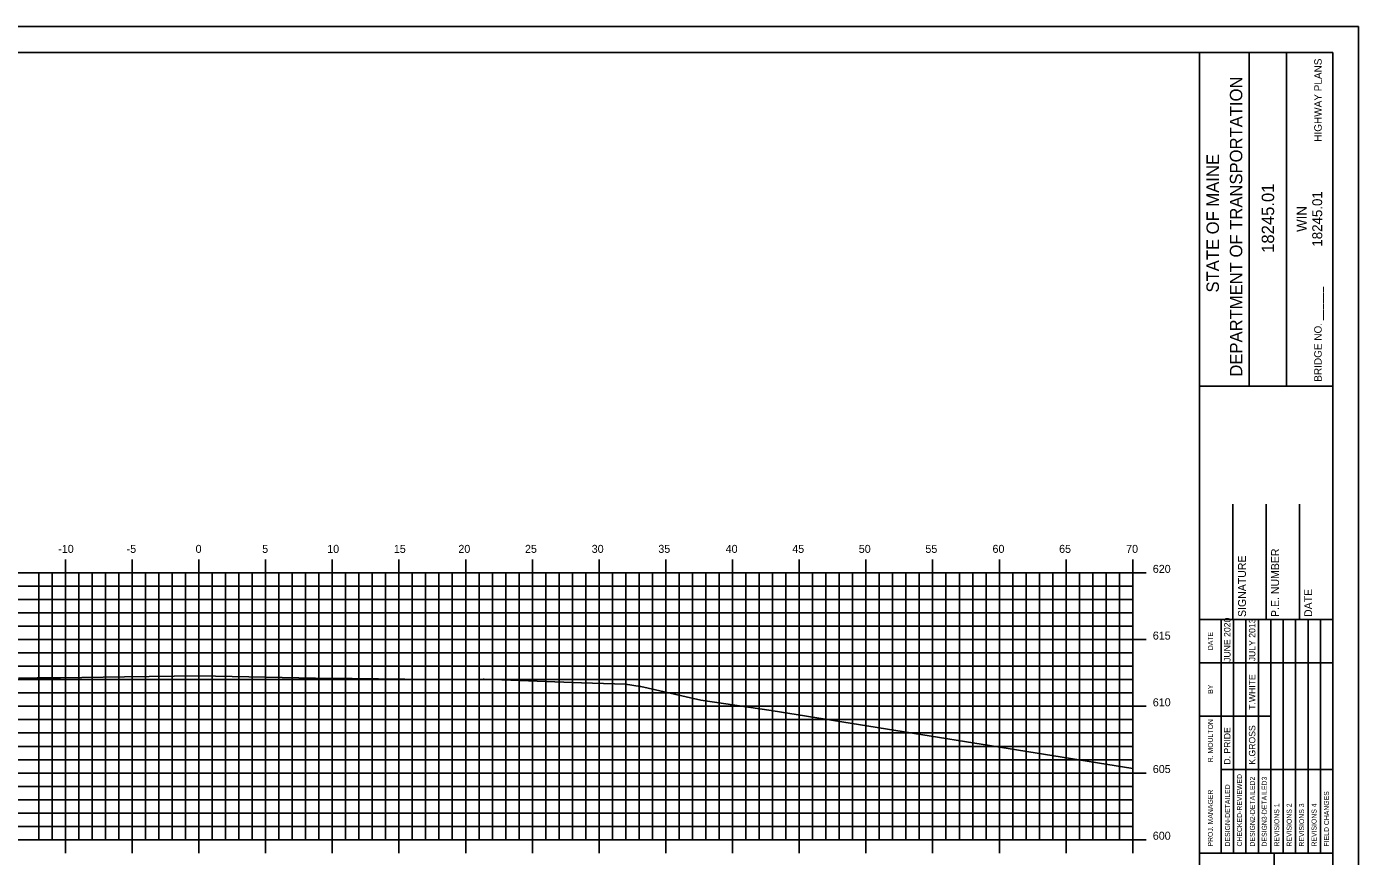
# Model space of a CAD drawing. Extents: x 1048806 to 1048976, y 780904 to 781014.
# Drawn here: x 1048876.1 to 1048975.9, y 780951.9 to 781014.1 of the extents above; entities that cross this region are included whole.
import ezdxf

# ---------------------------------------------------------------- set-up
doc = ezdxf.new("R2010")
doc.units = 0
for name, color, linetype in [('BORDER', 7, 'Continuous'), ('Default', 7, 'Continuous'), ('H_V ANNOTATION', 7, 'Continuous'), ('MAJOR', 7, 'Continuous'), ('MINOR', 7, 'Continuous'), ('S_Roadway_Centerline', 7, 'Continuous')]:
    doc.layers.add(name, color=color, linetype=linetype)

msp = doc.modelspace()

# ---------------------------------------------------------------- linework, layer by layer
at = {"layer": 'Default'}
for p, q in [((1048973.983, 781012.114), (1048813.983, 781012.114)), ((1048963.983, 780907.114), (1048963.983, 781012.117)), ((1048967.711, 780987.111), (1048967.711, 781012.111)), ((1048970.506, 780987.111), (1048970.506, 781012.111)), ((1048973.983, 780907.114), (1048973.983, 781012.114)), ((1048963.984, 780987.108), (1048973.983, 780987.108)), ((1048966.483, 780969.617), (1048966.483, 780978.265)), ((1048968.983, 780969.617), (1048968.983, 780978.265)), ((1048971.483, 780969.617), (1048971.483, 780978.265)), ((1048963.983, 780969.617), (1048973.983, 780969.617)), ((1048963.983, 780952.117), (1048973.983, 780952.117)), ((1048969.574, 780917.117), (1048969.574, 780952.117))]:
    msp.add_line(p, q, dxfattribs=at)
msp.add_lwpolyline([(1048805.889, 780904.055), (1048975.889, 780904.055), (1048975.889, 781014.055), (1048805.889, 781014.055)], close=True, dxfattribs=at)
for points in [[(1048965.598, 780966.367), (1048965.598, 780969.617)], [(1048966.53, 780952.12), (1048966.53, 780969.617)], [(1048967.462, 780969.617), (1048967.462, 780952.12)], [(1048968.394, 780952.12), (1048968.394, 780969.617)], [(1048969.325, 780952.12), (1048969.325, 780969.617)], [(1048970.257, 780952.12), (1048970.257, 780969.617)], [(1048971.189, 780952.12), (1048971.189, 780969.617)], [(1048972.12, 780952.12), (1048972.12, 780969.617)], [(1048973.052, 780952.12), (1048973.052, 780969.617)], [(1048965.599, 780952.12), (1048965.599, 780968.911)], [(1048963.983, 780966.367), (1048973.983, 780966.367)], [(1048963.983, 780962.367), (1048965.599, 780962.367)], [(1048965.598, 780962.367), (1048969.324, 780962.367)], [(1048965.598, 780958.367), (1048973.983, 780958.367)]]:
    msp.add_lwpolyline(points, dxfattribs=at)
at = {"layer": 'MAJOR'}
for p, q in [((1048878.983, 780974.116), (1048878.983, 780973.114)), ((1048883.983, 780974.116), (1048883.983, 780973.114)), ((1048888.983, 780974.116), (1048888.983, 780973.114)), ((1048893.983, 780974.116), (1048893.983, 780973.114)), ((1048898.983, 780974.116), (1048898.983, 780973.114)), ((1048903.983, 780974.116), (1048903.983, 780973.114)), ((1048908.983, 780974.116), (1048908.983, 780973.114)), ((1048913.983, 780974.116), (1048913.983, 780973.114)), ((1048918.983, 780974.116), (1048918.983, 780973.114)), ((1048923.983, 780974.116), (1048923.983, 780973.114)), ((1048928.983, 780974.116), (1048928.983, 780973.114)), ((1048933.983, 780974.116), (1048933.983, 780973.114)), ((1048938.983, 780974.116), (1048938.983, 780973.114)), ((1048943.983, 780974.116), (1048943.983, 780973.114)), ((1048948.983, 780974.116), (1048948.983, 780973.114)), ((1048953.983, 780974.116), (1048953.983, 780973.114)), ((1048958.983, 780974.116), (1048958.983, 780973.114)), ((1048818.983, 780973.114), (1048958.983, 780973.114)), ((1048818.983, 780973.114), (1048958.983, 780973.114)), ((1048878.983, 780953.114), (1048878.983, 780973.114)), ((1048883.983, 780953.114), (1048883.983, 780973.114)), ((1048888.983, 780953.114), (1048888.983, 780973.114)), ((1048893.983, 780953.114), (1048893.983, 780973.114)), ((1048898.983, 780953.114), (1048898.983, 780973.114)), ((1048903.983, 780953.114), (1048903.983, 780973.114)), ((1048908.983, 780953.114), (1048908.983, 780973.114)), ((1048913.983, 780953.114), (1048913.983, 780973.114)), ((1048918.983, 780953.114), (1048918.983, 780973.114)), ((1048923.983, 780953.114), (1048923.983, 780973.114)), ((1048928.983, 780953.114), (1048928.983, 780973.114)), ((1048933.983, 780953.114), (1048933.983, 780973.114)), ((1048938.983, 780953.114), (1048938.983, 780973.114)), ((1048943.983, 780953.114), (1048943.983, 780973.114)), ((1048948.983, 780953.114), (1048948.983, 780973.114)), ((1048953.983, 780953.114), (1048953.983, 780973.114)), ((1048959.985, 780973.114), (1048957.981, 780973.114)), ((1048958.983, 780953.114), (1048958.983, 780973.114)), ((1048958.983, 780953.114), (1048958.983, 780973.114)), ((1048818.983, 780968.114), (1048958.983, 780968.114)), ((1048959.985, 780968.114), (1048957.981, 780968.114)), ((1048818.983, 780963.114), (1048958.983, 780963.114)), ((1048959.985, 780963.114), (1048957.981, 780963.114)), ((1048818.983, 780958.114), (1048958.983, 780958.114)), ((1048959.985, 780958.114), (1048957.981, 780958.114)), ((1048818.983, 780953.114), (1048958.983, 780953.114)), ((1048818.983, 780953.114), (1048958.983, 780953.114)), ((1048878.983, 780952.112), (1048878.983, 780953.114)), ((1048883.983, 780952.112), (1048883.983, 780953.114)), ((1048888.983, 780952.112), (1048888.983, 780953.114)), ((1048893.983, 780952.112), (1048893.983, 780953.114)), ((1048898.983, 780952.112), (1048898.983, 780953.114)), ((1048903.983, 780952.112), (1048903.983, 780953.114)), ((1048908.983, 780952.112), (1048908.983, 780953.114)), ((1048913.983, 780952.112), (1048913.983, 780953.114)), ((1048918.983, 780952.112), (1048918.983, 780953.114)), ((1048923.983, 780952.112), (1048923.983, 780953.114)), ((1048928.983, 780952.112), (1048928.983, 780953.114)), ((1048933.983, 780952.112), (1048933.983, 780953.114)), ((1048938.983, 780952.112), (1048938.983, 780953.114)), ((1048943.983, 780952.112), (1048943.983, 780953.114)), ((1048948.983, 780952.112), (1048948.983, 780953.114)), ((1048953.983, 780952.112), (1048953.983, 780953.114)), ((1048959.985, 780953.114), (1048957.981, 780953.114)), ((1048958.983, 780952.112), (1048958.983, 780953.114))]:
    msp.add_line(p, q, dxfattribs=at)
at = {"layer": 'MINOR'}
for p, q in [((1048876.983, 780953.114), (1048876.983, 780973.114)), ((1048877.983, 780953.114), (1048877.983, 780973.114)), ((1048879.983, 780953.114), (1048879.983, 780973.114)), ((1048880.983, 780953.114), (1048880.983, 780973.114)), ((1048881.983, 780953.114), (1048881.983, 780973.114)), ((1048882.983, 780953.114), (1048882.983, 780973.114)), ((1048884.983, 780953.114), (1048884.983, 780973.114)), ((1048885.983, 780953.114), (1048885.983, 780973.114)), ((1048886.983, 780953.114), (1048886.983, 780973.114)), ((1048887.983, 780953.114), (1048887.983, 780973.114)), ((1048889.983, 780953.114), (1048889.983, 780973.114)), ((1048890.983, 780953.114), (1048890.983, 780973.114)), ((1048891.983, 780953.114), (1048891.983, 780973.114)), ((1048892.983, 780953.114), (1048892.983, 780973.114)), ((1048894.983, 780953.114), (1048894.983, 780973.114)), ((1048895.983, 780953.114), (1048895.983, 780973.114)), ((1048896.983, 780953.114), (1048896.983, 780973.114)), ((1048897.983, 780953.114), (1048897.983, 780973.114)), ((1048899.983, 780953.114), (1048899.983, 780973.114)), ((1048900.983, 780953.114), (1048900.983, 780973.114)), ((1048901.983, 780953.114), (1048901.983, 780973.114)), ((1048902.983, 780953.114), (1048902.983, 780973.114)), ((1048904.983, 780953.114), (1048904.983, 780973.114)), ((1048905.983, 780953.114), (1048905.983, 780973.114)), ((1048906.983, 780953.114), (1048906.983, 780973.114)), ((1048907.983, 780953.114), (1048907.983, 780973.114)), ((1048909.983, 780953.114), (1048909.983, 780973.114)), ((1048910.983, 780953.114), (1048910.983, 780973.114)), ((1048911.983, 780953.114), (1048911.983, 780973.114)), ((1048912.983, 780953.114), (1048912.983, 780973.114)), ((1048914.983, 780953.114), (1048914.983, 780973.114)), ((1048915.983, 780953.114), (1048915.983, 780973.114)), ((1048916.983, 780953.114), (1048916.983, 780973.114)), ((1048917.983, 780953.114), (1048917.983, 780973.114)), ((1048919.983, 780953.114), (1048919.983, 780973.114)), ((1048920.983, 780953.114), (1048920.983, 780973.114)), ((1048921.983, 780953.114), (1048921.983, 780973.114)), ((1048922.983, 780953.114), (1048922.983, 780973.114)), ((1048924.983, 780953.114), (1048924.983, 780973.114)), ((1048925.983, 780953.114), (1048925.983, 780973.114)), ((1048926.983, 780953.114), (1048926.983, 780973.114)), ((1048927.983, 780953.114), (1048927.983, 780973.114)), ((1048929.983, 780953.114), (1048929.983, 780973.114)), ((1048930.983, 780953.114), (1048930.983, 780973.114)), ((1048931.983, 780953.114), (1048931.983, 780973.114)), ((1048932.983, 780953.114), (1048932.983, 780973.114)), ((1048934.983, 780953.114), (1048934.983, 780973.114)), ((1048935.983, 780953.114), (1048935.983, 780973.114)), ((1048936.983, 780953.114), (1048936.983, 780973.114)), ((1048937.983, 780953.114), (1048937.983, 780973.114)), ((1048939.983, 780953.114), (1048939.983, 780973.114)), ((1048940.983, 780953.114), (1048940.983, 780973.114)), ((1048941.983, 780953.114), (1048941.983, 780973.114)), ((1048942.983, 780953.114), (1048942.983, 780973.114)), ((1048944.983, 780953.114), (1048944.983, 780973.114)), ((1048945.983, 780953.114), (1048945.983, 780973.114)), ((1048946.983, 780953.114), (1048946.983, 780973.114)), ((1048947.983, 780953.114), (1048947.983, 780973.114)), ((1048949.983, 780953.114), (1048949.983, 780973.114)), ((1048950.983, 780953.114), (1048950.983, 780973.114)), ((1048951.983, 780953.114), (1048951.983, 780973.114)), ((1048952.983, 780953.114), (1048952.983, 780973.114)), ((1048954.983, 780953.114), (1048954.983, 780973.114)), ((1048955.983, 780953.114), (1048955.983, 780973.114)), ((1048956.983, 780953.114), (1048956.983, 780973.114)), ((1048957.983, 780953.114), (1048957.983, 780973.114)), ((1048818.983, 780972.114), (1048958.983, 780972.114)), ((1048958.983, 780972.114), (1048957.981, 780972.114)), ((1048818.983, 780971.114), (1048958.983, 780971.114)), ((1048958.983, 780971.114), (1048957.981, 780971.114)), ((1048818.983, 780970.114), (1048958.983, 780970.114)), ((1048958.983, 780970.114), (1048957.981, 780970.114)), ((1048818.983, 780969.114), (1048958.983, 780969.114)), ((1048958.983, 780969.114), (1048957.981, 780969.114)), ((1048818.983, 780967.114), (1048958.983, 780967.114)), ((1048958.983, 780967.114), (1048957.981, 780967.114)), ((1048818.983, 780966.114), (1048958.983, 780966.114)), ((1048958.983, 780966.114), (1048957.981, 780966.114)), ((1048818.983, 780965.114), (1048958.983, 780965.114)), ((1048958.983, 780965.114), (1048957.981, 780965.114)), ((1048818.983, 780964.114), (1048958.983, 780964.114)), ((1048958.983, 780964.114), (1048957.981, 780964.114)), ((1048818.983, 780962.114), (1048958.983, 780962.114)), ((1048958.983, 780962.114), (1048957.981, 780962.114)), ((1048818.983, 780961.114), (1048958.983, 780961.114)), ((1048958.983, 780961.114), (1048957.981, 780961.114)), ((1048818.983, 780960.114), (1048958.983, 780960.114)), ((1048958.983, 780960.114), (1048957.981, 780960.114)), ((1048818.983, 780959.114), (1048958.983, 780959.114)), ((1048958.983, 780959.114), (1048957.981, 780959.114)), ((1048818.983, 780957.114), (1048958.983, 780957.114)), ((1048958.983, 780957.114), (1048957.981, 780957.114)), ((1048818.983, 780956.114), (1048958.983, 780956.114)), ((1048958.983, 780956.114), (1048957.981, 780956.114)), ((1048818.983, 780955.114), (1048958.983, 780955.114)), ((1048958.983, 780955.114), (1048957.981, 780955.114)), ((1048818.983, 780954.114), (1048958.983, 780954.114)), ((1048958.983, 780954.114), (1048957.981, 780954.114))]:
    msp.add_line(p, q, dxfattribs=at)
at = {"layer": 'S_Roadway_Centerline'}
msp.add_lwpolyline([(1048875.459, 780965.212), (1048876.871, 780965.253), (1048878.617, 780965.256), (1048883.421, 780965.315), (1048888.983, 780965.395), (1048898.978, 780965.205), (1048899.15, 780965.202), (1048900.483, 780965.187), (1048906.387, 780965.119), (1048910.301, 780965.154), (1048910.379, 780965.151), (1048917.666, 780964.876), (1048920.957, 780964.765), (1048922.073, 780964.592), (1048922.11, 780964.594), (1048926.597, 780963.587), (1048931.879, 780962.789), (1048958.983, 780958.45)], dxfattribs=at)

# ---------------------------------------------------------------- texts
at = {"layer": 'BORDER'}
for s, p in [('DEPARTMENT OF TRANSPORTATION', (1048967.19, 780987.82)), ('STATE OF MAINE', (1048965.438, 780994.126))]:
    msp.add_text(s, height=0.93176, rotation=90, dxfattribs=at).set_placement(p)
at = {"layer": 'Default'}
for s, height, p in [('HIGHWAY PLANS', 0.55901, (1048973.141, 781005.43)), ('18245.01', 0.9318, (1048969.575, 780997.099)), ('18245.01', 0.7453, (1048973.178, 780997.564)), ('WIN', 0.7453, (1048972.019, 780998.672)), ('BRIDGE NO. ______', 0.55901, (1048973.141, 780987.445)), ('SIGNATURE', 0.5906, (1048967.463, 780969.809)), ('P.E. NUMBER', 0.59055, (1048969.944, 780969.809)), ('DATE', 0.5906, (1048972.424, 780969.809)), ('JUNE 2020', 0.4845, (1048966.306, 780966.442)), ('JULY 2013', 0.4845, (1048968.169, 780966.489)), ('DATE', 0.3714, (1048964.987, 780967.323)), ('T.WHITE', 0.4845, (1048968.169, 780962.852)), ('BY', 0.3714, (1048964.987, 780964.052)), ('R. MOULTON', 0.3727, (1048964.987, 780958.92)), ('D. PRIDE', 0.4845, (1048966.306, 780958.74)), ('K.GROSS', 0.4845, (1048968.169, 780958.74)), ('DESIGN-DETAILED', 0.37275, (1048966.269, 780952.605)), ('CHECKED-REVIEWED', 0.37275, (1048967.164, 780952.605)), ('DESIGN2-DETAILED2', 0.37275, (1048968.133, 780952.605)), ('DESIGN3-DETAILED3', 0.37275, (1048969.027, 780952.605)), ('PROJ. MANAGER', 0.37275, (1048964.987, 780952.605)), ('FIELD CHANGES', 0.37275, (1048973.686, 780952.605)), ('REVISIONS 1', 0.37275, (1048969.959, 780952.605)), ('REVISIONS 2', 0.37275, (1048970.89, 780952.605)), ('REVISIONS 3', 0.37275, (1048971.822, 780952.605)), ('REVISIONS 4', 0.37275, (1048972.754, 780952.605))]:
    msp.add_text(s, height=height, rotation=90, dxfattribs=at).set_placement(p)
at = {"layer": 'H_V ANNOTATION'}
for s, p in [('-10', (1048878.447, 780974.614)), ('-5', (1048883.573, 780974.614)), ('0', (1048888.742, 780974.614)), ('5', (1048893.734, 780974.614)), ('10', (1048898.608, 780974.614)), ('15', (1048903.6, 780974.614)), ('20', (1048908.437, 780974.614)), ('25', (1048913.429, 780974.614)), ('30', (1048918.431, 780974.614)), ('35', (1048923.423, 780974.614)), ('40', (1048928.469, 780974.614)), ('45', (1048933.461, 780974.614)), ('50', (1048938.447, 780974.614)), ('55', (1048943.439, 780974.614)), ('60', (1048948.469, 780974.614)), ('65', (1048953.461, 780974.614)), ('70', (1048958.485, 780974.614)), ('620', (1048960.483, 780973.114)), ('615', (1048960.483, 780968.114)), ('610', (1048960.483, 780963.114)), ('605', (1048960.483, 780958.114)), ('600', (1048960.483, 780953.114))]:
    msp.add_text(s, height=0.6, dxfattribs=at).set_placement(p)
at = {"layer": 'S_Roadway_Centerline'}
for s, p in [('C', (1048888.978, 780965.395)), ('C', (1048888.978, 780965.395)), ('L', (1048888.983, 780965.388)), ('L', (1048888.983, 780965.388))]:
    msp.add_text(s, height=0.0146, dxfattribs=at).set_placement(p)

doc.saveas('drawing.dxf')
